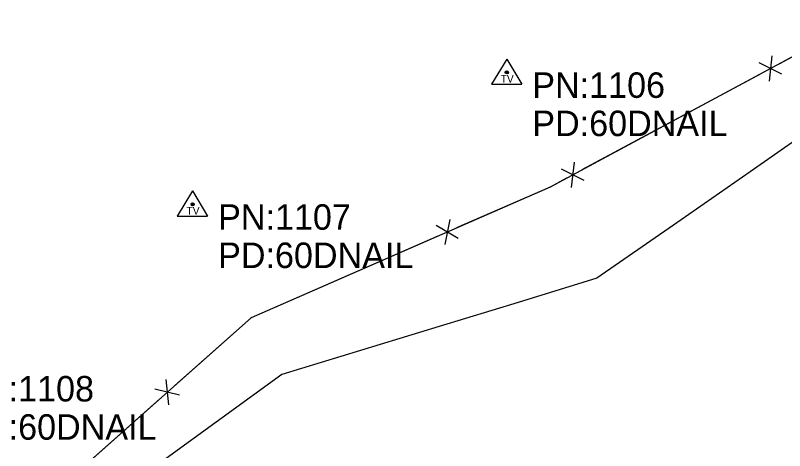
# Model space of a CAD drawing. Extents: x 1050807 to 1053552, y 395828 to 398415.
# Drawn here: x 1052207.8 to 1052358.5, y 396468 to 396553.4 of the extents above; entities that cross this region are included whole.
import ezdxf

# ---------------------------------------------------------------- set-up
doc = ezdxf.new("R2010")
doc.units = 0
for name, color, linetype in [('S_DITCHLINE', 7, 'Continuous'), ('S_FENCE', 7, 'Continuous'), ('S_MSC_PT_SYM', 7, 'Continuous'), ('S_SECONDARY_CTL', 7, 'Continuous'), ('S_SECONDARY_CTL_ANNOT', 7, 'Continuous')]:
    doc.layers.add(name, color=color, linetype=linetype)

msp = doc.modelspace()

# ---------------------------------------------------------------- linework, layer by layer
at = {"layer": 'S_DITCHLINE'}
msp.add_lwpolyline([(1052366.79, 396533.11), (1052351.77, 396522.67), (1052336.76, 396512.24), (1052321.74, 396501.8), (1052306.3, 396497.08), (1052290.87, 396492.35), (1052275.43, 396487.63), (1052259.99, 396482.91), (1052248.31, 396474.43), (1052236.63, 396465.95)], dxfattribs=at)
at = {"layer": 'S_FENCE'}
for p, q in [((1052375.15, 396553.36), (1052312.57, 396519.69)), ((1052356.07, 396545.42), (1052355.49, 396540.45)), ((1052356.07, 396545.42), (1052355.49, 396540.45)), ((1052358.01, 396541.81), (1052353.55, 396544.06)), ((1052358.01, 396541.81), (1052353.55, 396544.06)), ((1052317.33, 396524.57), (1052316.74, 396519.61)), ((1052317.33, 396524.57), (1052316.74, 396519.61)), ((1052319.27, 396520.96), (1052314.8, 396523.21)), ((1052319.27, 396520.96), (1052314.8, 396523.21)), ((1052312.57, 396519.69), (1052253.96, 396494.07)), ((1052294.55, 396509.58), (1052290.28, 396512.18)), ((1052294.55, 396509.58), (1052290.28, 396512.18)), ((1052292.91, 396513.33), (1052291.92, 396508.43)), ((1052292.91, 396513.33), (1052291.92, 396508.43)), ((1052253.96, 396494.07), (1052211.97, 396456.73)), ((1052237.23, 396481.94), (1052237.81, 396476.97)), ((1052237.23, 396481.94), (1052237.81, 396476.97)), ((1052239.96, 396478.88), (1052235.09, 396480.03)), ((1052239.96, 396478.88), (1052235.09, 396480.03))]:
    msp.add_line(p, q, dxfattribs=at)
for points in [[(1052375.15, 396553.36), (1052357.54, 396543.88)], [(1052375.15, 396553.36), (1052357.54, 396543.88)], [(1052354.02, 396541.99), (1052318.79, 396523.04)], [(1052354.02, 396541.99), (1052318.79, 396523.04)], [(1052315.77, 396521.41), (1052312.57, 396519.69)], [(1052315.77, 396521.41), (1052312.57, 396519.69)], [(1052312.57, 396519.69), (1052294.25, 396511.68)], [(1052312.57, 396519.69), (1052294.25, 396511.68)], [(1052290.59, 396510.08), (1052253.96, 396494.07)], [(1052290.59, 396510.08), (1052253.96, 396494.07)], [(1052253.96, 396494.07), (1052239.02, 396480.78)], [(1052253.96, 396494.07), (1052239.02, 396480.78)], [(1052236.03, 396478.12), (1052211.97, 396456.73)], [(1052236.03, 396478.12), (1052211.97, 396456.73)]]:
    msp.add_lwpolyline(points, dxfattribs=at)
at = {"layer": 'S_MSC_PT_SYM'}
for points in [[(1052312.57, 396519.69), (1052312.57, 396519.74), (1052312.57, 396519.69), (1052312.52, 396519.69), (1052312.57, 396519.69), (1052312.57, 396519.64), (1052312.57, 396519.69), (1052312.62, 396519.69)], [(1052253.96, 396494.07), (1052253.96, 396494.12), (1052253.96, 396494.07), (1052253.91, 396494.07), (1052253.96, 396494.07), (1052253.96, 396494.02), (1052253.96, 396494.07), (1052254.01, 396494.07)]]:
    msp.add_lwpolyline(points, dxfattribs=at)
at = {"layer": 'S_SECONDARY_CTL'}
for p, q in [((1052304.09, 396544.79), (1052301.08, 396539.84)), ((1052304.09, 396544.79), (1052307.04, 396539.84)), ((1052301.08, 396539.84), (1052307.04, 396539.84)), ((1052242.51, 396518.92), (1052239.5, 396513.96)), ((1052242.51, 396518.92), (1052245.46, 396513.96)), ((1052239.5, 396513.96), (1052245.46, 396513.96))]:
    msp.add_line(p, q, dxfattribs=at)
for centre, radius in [((1052304.09, 396542.18), 0.311), ((1052304.09, 396542.18), 0.183), ((1052304.09, 396542.18), 0.103), ((1052242.51, 396516.31), 0.311), ((1052242.51, 396516.31), 0.183), ((1052242.51, 396516.31), 0.103)]:
    msp.add_circle(centre, radius, dxfattribs=at)

# ---------------------------------------------------------------- texts
for p in [(1052302.89, 396540.17), (1052241.31, 396514.3)]:
    msp.add_text('TV', height=1.5, dxfattribs=at).set_placement(p)
at = {"layer": 'S_SECONDARY_CTL_ANNOT'}
for s, p in [('PN:1106', (1052309.09, 396537.18)), ('PD:60DNAIL', (1052309.09, 396529.68)), ('PN:1107', (1052247.51, 396511.31)), ('PD:60DNAIL', (1052247.51, 396503.81)), ('PN:1108', (1052197.16, 396477.64)), ('PD:60DNAIL', (1052197.16, 396470.14))]:
    msp.add_text(s, height=5, dxfattribs=at).set_placement(p)

doc.saveas('drawing.dxf')
